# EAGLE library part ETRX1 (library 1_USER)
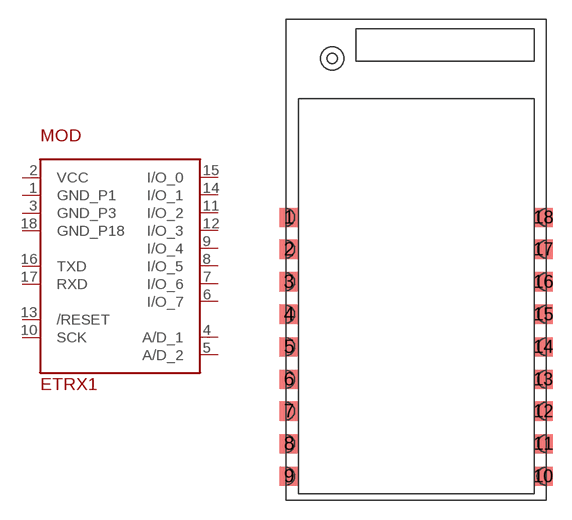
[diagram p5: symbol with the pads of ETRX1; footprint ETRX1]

Designator prefix MOD

## ETRX1  [ETRX1]
1  GND_P1  pwr
2  VCC  pwr
3  GND_P3  pwr
4  A/D_1
5  A/D_2
6  I/O_7
7  I/O_6
8  I/O_5
9  I/O_4
10  SCK
11  I/O_2
12  I/O_3
13  /RESET  in
14  I/O_1
15  I/O_0
16  TXD  out
17  RXD  in
18  GND_P18  pwr

## Footprint ETRX1 (pad centres in mm)
smd 1.5 x 1.5: 1 0.25,22.2; 2 0.25,19.7; 3 0.25,17.15; 4 0.25,14.6; 5 0.25,12.05; 6 0.25,9.5; 7 0.25,7; 8 0.25,4.45; 9 0.25,1.9; 10 20.2,1.9; 11 20.2,4.45; 12 20.2,7; 13 20.2,9.5; 14 20.2,12.05; 15 20.2,14.6; 16 20.2,17.15; 17 20.2,19.7; 18 20.2,22.2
